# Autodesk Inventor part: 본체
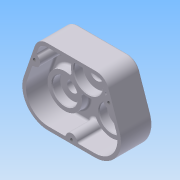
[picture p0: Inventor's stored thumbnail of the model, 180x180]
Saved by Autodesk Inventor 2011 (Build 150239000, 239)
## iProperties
Created: 2014-12
Part Number: 본체
Document SubType Name: Modeling
Designer: SDA24
Density: 2.71 g/cm^3
Material: 알루미늄-6061
Mass: 613.431 g
Surface Area: 665.191 cm^2
Volume: 226.358 cm^3
Author: SDA24
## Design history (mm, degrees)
sketch "스케치1"
  geometry: L1 (-47, 36)-(47, 36); L2 (0, 46)-(0, -46); L3 (0, 0)-(-32.527, -32.527); L4 (0, 0)-(32.527, -32.527); L5 (-47, 36)-(-66.565, -20.803); L6 (47, 36)-(66.565, -20.803); L7 (-32.527, -68.527)-(32.527, -68.527); A1 r 46 centre (0, 0) between (0, 46) and (0, -46); A2 r 36 centre (-32.527, -32.527) between (-66.565, -20.803) and (-32.527, -68.527); A3 r 36 centre (32.527, -32.527) between (32.527, -68.527) and (66.565, -20.803); 2 further points
  constraints: 14 end point, 8 point on circle, 4 midpoint, 3 centre point, 3 coincident, 2 horizontal, 2 perpendicular, 2 symmetric about line, 2 tangent, 1 point on line, 1 vertical alignment, 2 other
  dimensions: "d1" = 94 distance of L1.start L1.end; "d2" = 36 distance from line of point (0, 0) L1; "d3" = 92 diameter of A1; "d4" = 90 deg angle of L4 L3 (derived); "d5" = 72 diameter of A2
extrude "돌출1" new body sketch "스케치1" distance "d6" = 44; taper "d7" = 0 deg
fillet "모깎기1" dims "d8" = 18
feature "쉘1" dims "d9" = 5
sketch "스케치2"
  geometry: L1 (-27.675, -53.432)-(-12.291, -8.767) reference; L2 (66.689, -94.527)-(1.635, -94.527) reference; L3 (80.615, -8.767)-(95.999, -53.432) reference; L4 (0, 0)-(68.324, 0) reference; L5 (-27.675, -53.432)-(-12.291, -8.767) reference; L6 (66.689, -94.527)-(1.635, -94.527) reference; L7 (80.615, -8.767)-(95.999, -53.432) reference; L8 (0, 0)-(68.324, 0) reference; A1 r 13 centre (0, -13) between (0, 0) and (-12.291, -8.767) reference; A2 r 31 centre (1.635, -63.527) between (-27.675, -53.432) and (1.635, -94.527) reference; A3 r 31 centre (66.689, -63.527) between (66.689, -94.527) and (95.999, -53.432) reference; A4 r 13 centre (68.324, -13) between (80.615, -8.767) and (68.324, 0) reference; A5 r 13 centre (0, -13) between (0, 0) and (-12.291, -8.767) reference; A6 r 31 centre (1.635, -63.527) between (-27.675, -53.432) and (1.635, -94.527) reference; A7 r 31 centre (66.689, -63.527) between (66.689, -94.527) and (95.999, -53.432) reference; A8 r 13 centre (68.324, -13) between (80.615, -8.767) and (68.324, 0) reference; 1 further point
extrude "돌출2" join sketch "스케치2" distance "d10" = 5; taper "d11" = 0 deg
sketch "스케치3"
  geometry: L1 (66.689, -94.527)-(1.635, -94.527) reference; L2 (0, 5)-(68.324, 5) reference; L3 (80.615, -8.767)-(95.999, -53.432) reference; L4 (34.162, 5)-(34.162, -94.527); L5 (66.689, -94.527)-(1.635, -94.527) reference; L6 (-27.675, -53.432)-(-12.291, -8.767) reference; A1 r 8 centre (85.862, -24) between (83.257, -16.436) and (88.467, -31.564); A2 r 8 centre (34.162, -94.527) between (42.162, -94.527) and (26.162, -94.527); A3 r 8 centre (-17.538, -24) between (-20.143, -31.564) and (-14.933, -16.436); 3 further points
  constraints: 10 point on line, 6 point on circle, 3 centre point, 3 midpoint, 2 end point, 1 coincident, 1 vertical
  dimensions: "d12" = 29 distance from line of L2 point (85.862, -24); "d13" = 16 diameter of A1; "d14" = 29 distance from line of L2 A1.centre; "d15" = 16 diameter of A2; "d16" = 16 diameter of A3; "d17" = 29 distance from line of L2 A3.centre
extrude "돌출3" join sketch "스케치3" distance "d18" = 34; taper "d19" = 0 deg
sketch "스케치4"
  geometry: C1 r 24 at (34.162, -31); C2 r 24 at (1.635, -63.527); C3 r 24 at (66.689, -63.527); A1 r 31 centre (1.635, -63.527) between (-27.675, -53.432) and (1.635, -94.527) reference; A2 r 31 centre (66.689, -63.527) between (66.689, -94.527) and (95.999, -53.432) reference; 1 further point
  constraints: 3 centre point, 3 coincident
  dimensions: "d20" = 48 diameter of C1; "d21" = 48 diameter of C2; "d22" = 48 diameter of C3
extrude "돌출4" join sketch "스케치4" distance "d23" = 11; taper "d24" = 0 deg
sketch "스케치5"
  geometry: C1 r 20 at (-32.527, -32.527); C2 r 20 at (32.527, -32.527); A1 r 36 centre (-32.527, -32.527) between (-66.565, -20.803) and (-32.527, -68.527) reference; A2 r 36 centre (32.527, -32.527) between (32.527, -68.527) and (66.565, -20.803) reference; 1 further point
  constraints: 2 centre point, 2 coincident
  dimensions: "d25" = 40 diameter of C1; "d26" = 40 diameter of C2
extrude "돌출5" join sketch "스케치5" distance "d27" = 7; taper "d28" = -10 deg
sketch "스케치6"
  geometry: C1 r 18.766 at (0, 0) reference; C2 r 15 at (0, 0); 1 further point
  constraints: 1 centre point, 1 coincident
  dimensions: "d29" = 30 diameter of C2
extrude "돌출6" cut sketch "스케치6" distance "d30" = 7; taper "d31" = 0 deg
sketch "스케치7"
  geometry: C1 r 15 at (0, 0) reference; C2 r 7.75 at (0, 0); 1 further point
  constraints: 1 centre point, 1 coincident
  dimensions: "d32" = 15.5 diameter of C2
extrude "돌출7" cut sketch "스케치7" distance "d33" = 10; taper "d34" = 0 deg
sketch "스케치8"
  geometry: C1 r 17.5 at (66.689, -63.527); A1 r 24 centre (66.689, -63.527) between (45.578, -52.111) and (55.273, -42.416) reference
  constraints: 1 centre point, 1 coincident
  dimensions: "d35" = 35 diameter of C1
extrude "돌출8" cut sketch "스케치8" distance "d36" = 11; taper "d37" = 0 deg
sketch "스케치9"
  geometry: C1 r 17.5 at (1.635, -63.527); A1 r 24 centre (1.635, -63.527) between (13.051, -42.416) and (22.746, -52.111) reference
  constraints: 1 centre point, 1 coincident
  dimensions: "d38" = 35 diameter of C1
extrude "돌출9" cut sketch "스케치9" distance "d39" = 11; taper "d40" = 0 deg
sketch "스케치10"
  geometry: C1 r 17.5 at (0, 0) reference; C2 r 7.75 at (0, 0); 1 further point
  constraints: 1 centre point, 1 coincident
  dimensions: "d41" = 15.5 diameter of C2
extrude "돌출10" cut sketch "스케치10" distance "d42" = 10; taper "d43" = 0 deg
sketch "스케치11"
  geometry: C1 r 18.766 at (0, 0) reference; C2 r 15 at (0, 0); 1 further point
  constraints: 1 centre point, 1 coincident
  dimensions: "d44" = 30 diameter of C2
extrude "돌출11" cut sketch "스케치11" distance "d45" = 7; taper "d46" = 0 deg
sketch "스케치12"
  geometry: C1 r 20 at (34.162, -31); A1 r 24 centre (34.162, -31) between (22.746, -52.111) and (45.578, -52.111) reference
  constraints: 1 centre point, 1 coincident
  dimensions: "d47" = 40 diameter of C1
extrude "돌출12" cut sketch "스케치12" distance "d48" = 12; taper "d49" = 0 deg
sketch "스케치13"
  geometry: C1 r 20 at (0, 0) reference; C2 r 10 at (0, 0)
  constraints: 1 centre point, 1 coincident
  dimensions: "d50" = 20 diameter of C2
extrude "돌출13" cut sketch "스케치13" distance "d51" = 3; taper "d52" = 0 deg
chamfer "모따기1" distance "d53" = 1; stored, may be unused: second distance "d54" = 3.175, angle "d55" = 45 deg
fillet "모깎기2" dims "d56" = 3
fillet "모깎기3" dims "d57" = 3
fillet "모깎기4" dims "d58" = 3
fillet "모깎기5" dims "d59" = 3
fillet "모깎기6" dims "d60" = 3
fillet "모깎기7" dims "d61" = 3
fillet "모깎기8" dims "d62" = 0.3
fillet "모깎기9" dims "d63" = 0.1
sketch "스케치14"
  geometry: A1 r 8 centre (51.7, 7) between (47.131, 13.567) and (52.144, -0.988) reference; A2 r 8 centre (0, -63.527) between (7.697, -61.345) and (-7.697, -61.345) reference; A3 r 8 centre (-51.7, 7) between (-52.144, -0.988) and (-47.131, 13.567) reference; 4 further points
  constraints: 3 coincident
hole "Hole1" sketch "스케치14" at (-51.7, 7), (0, -63.527), (51.7, 7) diameter "d64" = 4.1402; stored, may be unused: countersink angle "d68" = 82 deg, drill point angle "d70" = 118 deg; dims "d65" = 20, "d66" = 9.525, "d67" = 6.35, "d69" = 23
node "작업 평면1"
sketch "스케치15"
  geometry: L1 (34.162, 36)-(-34.162, 36) reference; 2 further points
  constraints: 1 vertical alignment, 1 other
  dimensions: "d74" = 30 distance from line of L1 point (0, 6)
feature "엠보싱1" sketch "스케치15" dims "d1" = 94, "d2" = 36, "d3" = 92, "d4" = 90 deg (derived), "d5" = 72, "d65" = 20, "d75" = 1, "d76" = 0
fillet "모깎기10" dims "d77" = 0.3
node "솔리드1"
node "투영된 루프1"
other parameters: "d71" = -33.3375
